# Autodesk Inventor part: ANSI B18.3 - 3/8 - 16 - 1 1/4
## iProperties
Comments: To add or edit properties for Autodesk Inventor files, use iProperties.
Created: 2005-06
Part Number: ANSI B18.3 - 3/8 - 16 - 1 1/4
Vendor: Autodesk Inc.
Document SubType Name: Modeling
Designer: John Blackburn
Material: Default
Description: Hexagon Socket Head Cap Screw
Standard: ANSI B18.3
Alert: To add or edit properties for Autodesk Inventor files, use iProperties.
Control State: 0
Master: False
Checked Out: False
Shininess: 64.0
Length Units: 11272
Angle Units: 11279
Time Units: 11290
Mass Units: 11286
Length Display Precision: 3
Angle Display Precision: 2
Compacted: True
EGR: 3
Classification: un/spsc 31161501
Density: 0.0
Volumn: 0.0
Area: 0.0
PropertySet Name: Model Information
Author: John Blackburn
Revision Number: 8
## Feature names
1. Body [Revolution]
2. Slot [Extrusion]
3. Fillet1
4. Chamfer1
